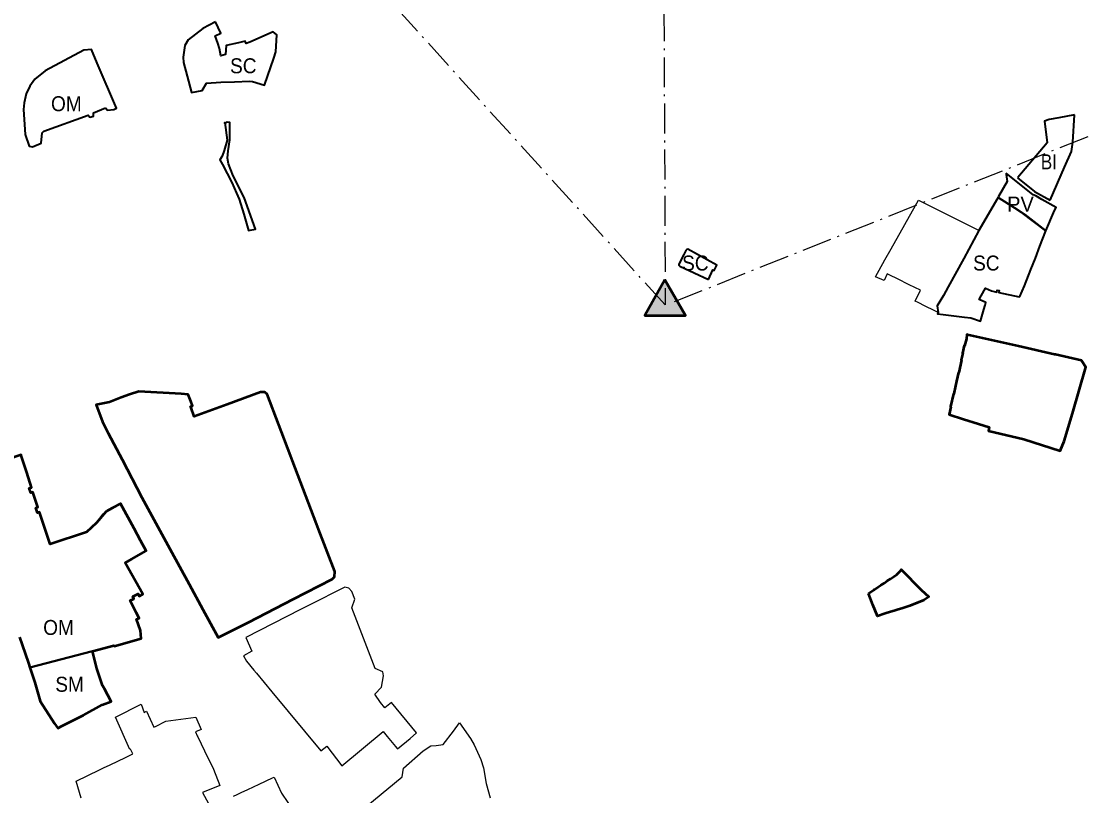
# Model space of a CAD drawing. Extents: x -650276 to -642489, y -1074311 to -1066720.
# Drawn here: x -647583 to -646730, y -1070993 to -1070373 of the extents above; entities that cross this region are included whole.
import ezdxf

# ---------------------------------------------------------------- set-up
doc = ezdxf.new("R2010")
doc.units = 0
doc.header["$LTSCALE"] = 4.8
doc.linetypes.add('DOT_DASHED', pattern=[7.7, 5, -1.2, 0.3, -1.2])
for name, color, linetype, lineweight in [('12', 7, 'Continuous', 35), ('15', 7, 'Continuous', 35), ('17', 7, 'Continuous', 35), ('18', 7, 'Continuous', 35), ('2', 7, 'Continuous', 35), ('55', 7, 'Continuous', 53), ('60', 7, 'Continuous', 53), ('61', 7, 'Continuous', 25)]:
    doc.layers.add(name, color=color, linetype=linetype, lineweight=lineweight)
doc.layers.add('62', color=7, linetype='Continuous')

msp = doc.modelspace()

# ---------------------------------------------------------------- hatches: boundary and pattern name
at = {"layer": '55'}
msp.add_hatch(color=256, dxfattribs=at).paths.add_polyline_path([(-647067.857, -1070579.969), (-647083.808, -1070608.615), (-647051.424, -1070608.615)])

# ---------------------------------------------------------------- linework, layer by layer
at = {"layer": '12'}
msp.add_lwpolyline([(-647515.73, -1070442.32), (-647514.23, -1070444.18), (-647509.22, -1070443.62), (-647506.95, -1070442.71), (-647522.54, -1070406.51), (-647527.1, -1070395.72), (-647533.1, -1070396.26), (-647564.01, -1070412.59), (-647572.37, -1070419.41), (-647576.48, -1070425.09), (-647579.22, -1070431.05), (-647581.04, -1070438.4), (-647581.54, -1070443.7), (-647580.1, -1070463.69), (-647576.92, -1070473), (-647574.28, -1070473.46), (-647567.32, -1070470.66), (-647566.55, -1070462.22), (-647565.11, -1070461.12), (-647529.74, -1070448.27), (-647528.28, -1070449.87), (-647525.54, -1070448.89), (-647525.45, -1070446.21)], close=True, dxfattribs=at)
msp.add_lwpolyline([(-647515.73, -1070442.32), (-647514.23, -1070444.18), (-647509.22, -1070443.62), (-647506.95, -1070442.71), (-647522.54, -1070406.51), (-647527.1, -1070395.72), (-647533.1, -1070396.26), (-647564.01, -1070412.59), (-647572.37, -1070419.41), (-647576.48, -1070425.09), (-647579.22, -1070431.05), (-647581.04, -1070438.4), (-647581.54, -1070443.7), (-647580.1, -1070463.69), (-647576.92, -1070473), (-647574.28, -1070473.46), (-647567.32, -1070470.66), (-647566.55, -1070462.22), (-647565.11, -1070461.12), (-647529.74, -1070448.27), (-647528.28, -1070449.87), (-647525.54, -1070448.89), (-647525.45, -1070446.21)], close=True, dxfattribs=at)
msp.add_lwpolyline([(-647515.73, -1070442.32), (-647514.23, -1070444.18), (-647509.22, -1070443.62), (-647506.95, -1070442.71), (-647522.54, -1070406.51), (-647527.1, -1070395.72), (-647533.1, -1070396.26), (-647564.01, -1070412.59), (-647572.37, -1070419.41), (-647576.48, -1070425.09), (-647579.22, -1070431.05), (-647581.04, -1070438.4), (-647581.54, -1070443.7), (-647580.1, -1070463.69), (-647576.92, -1070473), (-647574.28, -1070473.46), (-647567.32, -1070470.66), (-647566.55, -1070462.22), (-647565.11, -1070461.12), (-647529.74, -1070448.27), (-647528.28, -1070449.87), (-647525.54, -1070448.89), (-647525.45, -1070446.21)], close=True, dxfattribs=at)
for points in [[(-647569.92, -1070762.24), (-647573.88, -1070750.25), (-647575.58, -1070750.83), (-647576.81, -1070746.86), (-647575.09, -1070746.33), (-647578.79, -1070734.33), (-647583.38, -1070720.9), (-647583.22, -1070720.2), (-647593.6, -1070723.68), (-647610.33, -1070729.28), (-647600.53, -1070758.65), (-647619.2, -1070764.85), (-647617.36, -1070770.69)], [(-647584.6, -1070866.3), (-647580.22, -1070879.3), (-647578.703, -1070883.851), (-647578.703, -1070883.851), (-647576.469, -1070890.564), (-647526.13, -1070877.41), (-647509.1, -1070872.96), (-647508.96, -1070873.41), (-647487.16, -1070867.32), (-647487.91, -1070860.91), (-647490.92, -1070851.82), (-647488.8, -1070851.12), (-647494.1, -1070840.58), (-647495.93, -1070836.86), (-647493.16, -1070835.5), (-647494.03, -1070833.64), (-647489.55, -1070831.53), (-647488.75, -1070833.37), (-647485.9, -1070832), (-647500.07, -1070806.87), (-647500.07, -1070806.87), (-647483.16, -1070797.07), (-647492.81, -1070779.18), (-647492.81, -1070779.18), (-647497.227, -1070771.165), (-647503.76, -1070759.31), (-647514.49, -1070764.93), (-647517.61, -1070767.89), (-647523.07, -1070774.86), (-647531.05, -1070782.23), (-647560.06, -1070791.72), (-647566.26, -1070773.148)], [(-647570.27, -1070766.86), (-647571.63, -1070762.82), (-647569.92, -1070762.24)], [(-647566.26, -1070773.148), (-647568.55, -1070766.29), (-647570.27, -1070766.86)]]:
    msp.add_lwpolyline(points, dxfattribs=at)
at = {"layer": '15'}
msp.add_lwpolyline([(-647404.96, -1070527.57), (-647401.35, -1070540.59), (-647395.75, -1070539.47), (-647404.879, -1070514.114), (-647413.552, -1070496.671), (-647417.297, -1070487.185), (-647418.038, -1070482.516), (-647417.482, -1070476.846), (-647416.37, -1070468.064), (-647416.148, -1070454.055), (-647418.49, -1070453.76), (-647420.13, -1070454.78), (-647420.22, -1070454.02), (-647418.41, -1070468.21), (-647420.74, -1070476.57), (-647422.285, -1070480.931), (-647424.226, -1070484.029), (-647422.19, -1070487.75), (-647414.6, -1070502.16), (-647410.86, -1070510.68), (-647408.82, -1070515.49)], close=True, dxfattribs=at)
for points in [[(-646794.59, -1070494.62), (-646794.53, -1070495.7), (-646793.75, -1070501.26), (-646800.6, -1070513.43), (-646800.94, -1070514.04)], [(-646755.84, -1070524.5), (-646754.52, -1070522.08), (-646765.96, -1070515.75), (-646770.95, -1070512.94), (-646773, -1070511.96), (-646794.59, -1070494.62)], [(-646800.94, -1070514.04), (-646788, -1070522.49), (-646782.63, -1070526.02)], [(-646782.63, -1070526.02), (-646779.68, -1070527.87), (-646762.71, -1070540.85), (-646755.84, -1070524.5)]]:
    msp.add_lwpolyline(points, dxfattribs=at)
at = {"layer": '17'}
for points in [[(-647427.8, -1070373.32), (-647437.76, -1070378.66), (-647449.69, -1070387.83), (-647452.17, -1070392.38), (-647453.71, -1070401.81), (-647453.35, -1070406.09), (-647450.51, -1070416.96), (-647446.93, -1070429.99), (-647438.45, -1070428.47), (-647434.85, -1070422.64), (-647423.38, -1070421.87), (-647412.51, -1070421.5), (-647400.41, -1070421.08), (-647398.21, -1070421.15), (-647388.6, -1070424.24), (-647381.11, -1070402.45), (-647379.3, -1070397.57), (-647378.49, -1070383.91), (-647381.65, -1070381.45), (-647400.22, -1070389.64), (-647403.27, -1070390.91), (-647404, -1070388.84), (-647409.36, -1070390.24), (-647419.08, -1070392.52), (-647419.68, -1070399.59), (-647423.58, -1070400.59), (-647424.54, -1070394.78), (-647425.99, -1070390.47), (-647427.96, -1070384.64), (-647423.57, -1070382.64)], [(-646802.19, -1070516.26), (-646816.42, -1070540.49), (-646828.45, -1070562.89), (-646841.16, -1070585.79), (-646844.76, -1070592.54), (-646849.72, -1070600.98), (-646848.99, -1070606.28), (-646849.59, -1070607.4), (-646844.96, -1070607.98), (-646827.88, -1070610.12), (-646822.99, -1070610.51), (-646815.05, -1070613.14), (-646812.5, -1070603.78), (-646811.5, -1070600.29), (-646810.82, -1070598.23), (-646816.11, -1070595.8), (-646814.52, -1070592.78), (-646811.06, -1070586.67), (-646806.41, -1070589), (-646802.06, -1070589.93), (-646801.73, -1070588.37), (-646800.13, -1070588.71), (-646800.47, -1070590.28), (-646784.18, -1070593.76), (-646784, -1070593.34), (-646783.59, -1070593.52), (-646779.9, -1070584.92), (-646774.91, -1070571.88), (-646771.17, -1070562.7), (-646767.63, -1070553.09), (-646762.71, -1070540.85), (-646782.63, -1070526.02), (-646788, -1070522.49), (-646800.94, -1070514.04)], [(-647033.01, -1070579.83), (-647029.44, -1070572.13), (-647028.52, -1070572.63), (-647026.14, -1070568.26), (-647049.52, -1070555.64), (-647050.37, -1070555.74), (-647051.14, -1070556.59), (-647052.77, -1070559.7), (-647056.79, -1070567.41), (-647056.8, -1070568.32), (-647055.79, -1070569.07)]]:
    msp.add_lwpolyline(points, close=True, dxfattribs=at)
at = {"layer": '18'}
for points in [[(-647511.37, -1070917.79), (-647516.66, -1070907.8), (-647518.12, -1070905.05), (-647522.74, -1070891.48), (-647526.13, -1070877.41), (-647576.469, -1070890.564)], [(-647576.469, -1070890.564), (-647576.43, -1070890.68), (-647575.35, -1070893.91), (-647574.09, -1070897.7), (-647572.32, -1070902.72), (-647568.2, -1070917.54), (-647556.52, -1070935.59), (-647553.94, -1070939.11)], [(-647553.94, -1070939.11), (-647553.94, -1070939.11), (-647550.59, -1070937.45), (-647533.31, -1070928.79), (-647518.35, -1070920.62)], [(-647518.35, -1070920.62), (-647514.7, -1070918.79), (-647511.37, -1070917.79)]]:
    msp.add_lwpolyline(points, dxfattribs=at)
at = {"layer": '2'}
for points in [[(-646739.74, -1070447.98), (-646752.29, -1070450.28), (-646760.03, -1070451.56), (-646763.94, -1070452.95), (-646761.8, -1070470.4), (-646785.15, -1070498.05), (-646785.5, -1070498.47)], [(-646759.42, -1070516.37), (-646747.89, -1070489.87), (-646742.37, -1070477.2), (-646741.33, -1070469.79), (-646739.74, -1070447.98)], [(-646785.5, -1070498.47), (-646771.9, -1070509.4), (-646759.42, -1070516.37)]]:
    msp.add_lwpolyline(points, dxfattribs=at)
at = {"layer": '55', "linetype": 'DOT_DASHED', "lineweight": 25}
for p, q in [((-647072.859, -1069440.93), (-647067.564, -1070600.224)), ((-647067.564, -1070600.224), (-647577.112, -1070037.236)), ((-647060.176, -1070597.455), (-645765.418, -1070080.935))]:
    msp.add_line(p, q, dxfattribs=at)
at = {"layer": '55'}
msp.add_lwpolyline([(-647067.857, -1070579.969), (-647083.808, -1070608.615), (-647051.424, -1070608.615)], close=True, dxfattribs=at)
at = {"layer": '60'}
for points in [[(-646825.54, -1070624.03), (-646826.12, -1070623.9), (-646826.45, -1070627.3), (-646827.98, -1070632.83), (-646828.22, -1070632.77), (-646829.55, -1070638.78), (-646829.55, -1070638.78), (-646829.3, -1070638.83), (-646830.51, -1070644.3), (-646830.26, -1070644.35), (-646832.46, -1070654.31), (-646832.7, -1070654.26), (-646834.27, -1070661.39), (-646834.27, -1070661.39), (-646834.4, -1070661.35), (-646835.23, -1070665.08), (-646835.1, -1070665.12), (-646836.6, -1070671.54), (-646836.6, -1070671.54), (-646836.87, -1070671.46), (-646839.27, -1070681.62), (-646838.96, -1070681.72), (-646840.36, -1070687.86), (-646828.7, -1070691.73), (-646816.84, -1070695.43), (-646808.09, -1070698.19), (-646808.76, -1070701.11), (-646780.44, -1070707.59), (-646751.23, -1070717), (-646748.04, -1070709.23), (-646741.52, -1070687.22), (-646730.66, -1070650.07), (-646734.18, -1070644.6), (-646755.21, -1070639.87), (-646755.84, -1070639.88), (-646784.62, -1070633.19)], [(-647365.48, -1070835.85), (-647334.27, -1070819.86), (-647332.51, -1070817.97), (-647332.25, -1070813.72), (-647345.18, -1070779.89), (-647346.96, -1070775.41), (-647365.94, -1070725.08), (-647367.67, -1070720.73), (-647377.04, -1070696.22), (-647386.39, -1070671.74), (-647388.31, -1070669.95), (-647391.74, -1070670.16), (-647418.28, -1070679.89), (-647444.78, -1070689.6), (-647447.31, -1070682.72), (-647447.76, -1070681.5), (-647446.22, -1070680.91), (-647447.58, -1070677.36), (-647449.69, -1070671.81), (-647455.17, -1070671.48), (-647489.21, -1070669.41), (-647496.64, -1070671.93), (-647503.3, -1070674.3), (-647512.51, -1070677.98), (-647523.27, -1070680.11), (-647518.19, -1070693.93), (-647513.59, -1070702.8), (-647502.59, -1070724.13), (-647486.84, -1070754.54), (-647464.3, -1070795.6), (-647448.84, -1070823.79), (-647437.79, -1070844.12), (-647425.58, -1070866.7), (-647401.15, -1070854.25)], [(-646904.8, -1070831.23), (-646900.57, -1070828.42), (-646900.09, -1070828.1), (-646897.34, -1070826.28), (-646894.84, -1070824.62), (-646892.34, -1070822.96), (-646889.85, -1070821.3), (-646887.3, -1070819.61), (-646884.68, -1070817.87), (-646882.18, -1070816.21), (-646878.66, -1070812.72), (-646878.61, -1070812.14), (-646862.56, -1070828.29), (-646856.41, -1070834.13), (-646860.55, -1070836.71), (-646871.78, -1070841.33), (-646875.05, -1070842.32), (-646878.26, -1070843.29), (-646881.11, -1070844.21), (-646884.27, -1070845.17), (-646887.32, -1070846.14), (-646891.42, -1070847.44), (-646897.71, -1070849.39), (-646901.26, -1070840.31)]]:
    msp.add_lwpolyline(points, close=True, dxfattribs=at)
msp.add_lwpolyline([(-647584.6, -1070866.3), (-647580.22, -1070879.3), (-647577.59, -1070887.19), (-647576.43, -1070890.68), (-647575.35, -1070893.91), (-647574.09, -1070897.7), (-647572.32, -1070902.72), (-647568.2, -1070917.54), (-647556.52, -1070935.59), (-647553.94, -1070939.11), (-647550.59, -1070937.45), (-647533.31, -1070928.79), (-647518.35, -1070920.62), (-647511.37, -1070917.79), (-647516.66, -1070907.8), (-647518.12, -1070905.05), (-647522.74, -1070891.48), (-647526.13, -1070877.41), (-647509.1, -1070872.96), (-647508.96, -1070873.41), (-647487.16, -1070867.32), (-647487.91, -1070860.91), (-647490.92, -1070851.82), (-647488.8, -1070851.12), (-647491.19, -1070846.49), (-647492.48, -1070843.88), (-647494.1, -1070840.58), (-647495.93, -1070836.86), (-647493.16, -1070835.5), (-647494.03, -1070833.64), (-647489.55, -1070831.53), (-647488.75, -1070833.37), (-647485.9, -1070832), (-647500.07, -1070806.87), (-647500.07, -1070806.87), (-647494.88, -1070803.86), (-647483.16, -1070797.07), (-647487.67, -1070788.86), (-647492.81, -1070779.18), (-647503.76, -1070759.31), (-647515.216, -1070765.619), (-647523.07, -1070774.86), (-647531.05, -1070782.23), (-647560.06, -1070791.72), (-647568.55, -1070766.29), (-647570.27, -1070766.86), (-647571.63, -1070762.82), (-647569.92, -1070762.24), (-647573.88, -1070750.25), (-647575.58, -1070750.83), (-647576.81, -1070746.86), (-647575.09, -1070746.33), (-647578.79, -1070734.33), (-647583.38, -1070720.9), (-647583.22, -1070720.2), (-647593.6, -1070723.68)], dxfattribs=at)
at = {"layer": '61'}
for points in [[(-646867.54, -1070597.11), (-646863.26, -1070588.3), (-646872.19, -1070583.97), (-646876.02, -1070582.12), (-646877.88, -1070581.22), (-646879.541, -1070580.417), (-646889.9, -1070575.41), (-646892.4, -1070580.64), (-646899.2, -1070577.61), (-646891.65, -1070564.15), (-646886.72, -1070555.37), (-646864.73, -1070516.2), (-646816.66, -1070540.37), (-646816.42, -1070540.49), (-646828.45, -1070562.89), (-646838.95, -1070581.53), (-646841.16, -1070585.79), (-646844.76, -1070592.54), (-646849.72, -1070600.98), (-646849.72, -1070600.98), (-646848.99, -1070606.28), (-646852.3, -1070604.63), (-646859.48, -1070601.1), (-646865.02, -1070598.34)], [(-647299.98, -1070891.49), (-647318.68, -1070842.72), (-647316.06, -1070835.75), (-647318.44, -1070829.76), (-647321.01, -1070827.14), (-647324.15, -1070826.29), (-647331.02, -1070829.74), (-647345.71, -1070837.13), (-647359.71, -1070844.27), (-647403.51, -1070866.6), (-647398.52, -1070877.49), (-647405.34, -1070881.23), (-647402.82, -1070885.66), (-647396.9, -1070892.8), (-647394.88, -1070895.23), (-647382.57, -1070910.05), (-647343.34, -1070957.27), (-647338.57, -1070953.63), (-647326.51, -1070969.42), (-647293.51, -1070942.01), (-647290.28, -1070945.89), (-647283.54, -1070954.02), (-647282.46, -1070955.31), (-647281.97, -1070955.9), (-647271.95, -1070947.47), (-647266.79, -1070942.95), (-647286.92, -1070918.59), (-647292.14, -1070922.88), (-647295.69, -1070918.55), (-647300.07, -1070911.99), (-647294.73, -1070906.32), (-647293.09, -1070897.18), (-647293.7, -1070893.99)]]:
    msp.add_lwpolyline(points, close=True, dxfattribs=at)
for points in [[(-647535.19, -1070995.23), (-647539.38, -1070981.6), (-647520.58, -1070972.61), (-647517.43, -1070971.1), (-647511.96, -1070968.48), (-647499.8, -1070962.67), (-647493.79, -1070959.8), (-647495.91, -1070955.93), (-647496.37, -1070956.17), (-647507.79, -1070930.48), (-647487.33, -1070919.95), (-647484.78, -1070926.54), (-647483.02, -1070925.66), (-647477.21, -1070938.44), (-647475.82, -1070937.77), (-647467.47, -1070933.53), (-647443.36, -1070930.41), (-647439.33, -1070940.28), (-647443.84, -1070942.26), (-647442.33, -1070945.38), (-647441.9, -1070946.28), (-647436.58, -1070957.29), (-647429.44, -1070972.06), (-647424.16, -1070985.19), (-647438.05, -1070990.74), (-647431.74, -1071002.56)], [(-647317.99, -1071010.98), (-647278.2, -1070978.19), (-647277.18, -1070971.26), (-647261.35, -1070957.45), (-647255.21, -1070953.46), (-647251.11, -1070953.01), (-647245.32, -1070952.38), (-647237.16, -1070941.5), (-647232.24, -1070934.94), (-647223.65, -1070947.55), (-647220.46, -1070952.68), (-647215.29, -1070964.36), (-647213.23, -1070970.92), (-647210.97, -1070983.56), (-647207.77, -1070995.03)], [(-647413.35, -1070993.67), (-647410.26, -1070992.23), (-647407.22, -1070990.81), (-647401.93, -1070988.34), (-647392.83, -1070984.14), (-647382.05, -1070979.01), (-647380.69, -1070978.37), (-647374.95, -1070991.15), (-647364.66, -1071006.25)]]:
    msp.add_lwpolyline(points, dxfattribs=at)

# ---------------------------------------------------------------- texts
at = {"layer": '62'}
for s, width, p in [('SC', 0.95, (-647416.06, -1070414.645)), ('OM', 0.95, (-647559.43, -1070445.015)), ('BI', 0.85, (-646766.828, -1070491.569)), ('SC', 0.95, (-647054.06, -1070572.645)), ('SC', 0.95, (-646821.06, -1070572.645)), ('OM', 0.95, (-647565.708, -1070864.552)), ('SM', 0.95, (-647556.006, -1070910.054))]:
    msp.add_text(s, height=12, dxfattribs=dict(at, width=width)).set_placement(p)
msp.add_text('PV', height=12, dxfattribs=at).set_placement((-646793.831, -1070525.433))

doc.saveas('drawing.dxf')
